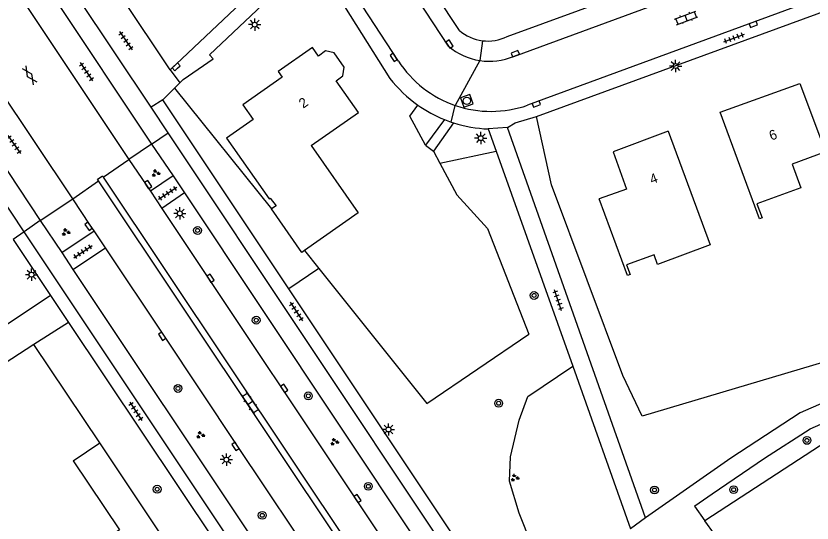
# Model space of a CAD drawing. Extents: x 137999 to 141000, y 397500 to 400501.
# Drawn here: x 138292.8 to 138374, y 399809 to 399860.8 of the extents above; entities that cross this region are included whole.
import ezdxf

# ---------------------------------------------------------------- set-up
doc = ezdxf.new("R2010")
doc.units = 0
for name, color, linetype in [('gg-afsc-erfafscheiding', 7, 'Continuous'), ('gg-afsc-hekwerk', 7, 'Continuous'), ('gg-anno-huisnummerreeks BGT', 7, 'Continuous'), ('gg-bbg-gedigitaliseerde bebouwing', 7, 'Continuous'), ('gg-bbg-hoofdgebouw', 7, 'Continuous'), ('gg-knt-verharding', 7, 'Continuous'), ('gt-grn-groengrens', 7, 'Continuous'), ('gt-grn-groengrens NZ', 7, 'Continuous'), ('gt-grn-weggrens', 7, 'Continuous'), ('gt-symb-boom', 7, 'Continuous'), ('gt-symb-gesloten verharding', 7, 'Continuous'), ('gt-symb-groenvak', 7, 'Continuous'), ('gt-symb-klinker verharding', 7, 'Continuous'), ('gt-symb-kolk', 7, 'Continuous'), ('gt-symb-lichtmast', 7, 'Continuous'), ('gt-symb-rioolschacht', 7, 'Continuous'), ('gt-symb-tegel verharding', 7, 'Continuous')]:
    doc.layers.add(name, color=color, linetype=linetype)

# ---------------------------------------------------------------- blocks, each defined once
blk = doc.blocks.new('gt0-LMAST')
at = {"layer": 'gt-symb-lichtmast'}
for p, q in [((-0.182, 0.173), (-0.447, 0.438)), ((-0.005, 0.246), (-0.005, 0.621)), ((0.172, 0.173), (0.437, 0.438)), ((-0.255, -0.004), (-0.63, -0.004)), ((-0.182, -0.181), (-0.447, -0.446)), ((-0.005, -0.254), (-0.005, -0.629)), ((0.437, -0.446), (0.172, -0.181)), ((0.245, -0.004), (0.62, -0.004))]:
    blk.add_line(p, q, dxfattribs=at)
blk.add_circle((-0.005, -0.004), 0.25, dxfattribs=at)
blk = doc.blocks.new('gt0-TEG1')
at = {"layer": 'gt-symb-tegel verharding'}
for p, q in [((-1.125, 0), (1.125, 0)), ((-0.9, -0.25), (-0.9, 0.25)), ((-0.45, -0.25), (-0.45, 0.25)), ((0, -0.25), (0, 0.25)), ((0.45, -0.25), (0.45, 0.25)), ((0.9, -0.25), (0.9, 0.25))]:
    blk.add_line(p, q, dxfattribs=at)
blk = doc.blocks.new('gt0-KOLK')
at = {"layer": 'gt-symb-kolk'}
blk.add_lwpolyline([(0, 0), (0.375, 0), (0.375, 0.4), (-0.375, 0.4), (-0.375, 0), (0, 0)], dxfattribs=at)
blk = doc.blocks.new('gt0-KL1')
at = {"layer": 'gt-symb-klinker verharding'}
for p, q in [((-1.15, 0.3), (1.15, 0.3)), ((-1, -0.3), (-1, 0.3)), ((-0.5, 0.3), (-0.5, 0.45)), ((0, -0.3), (0, 0.3)), ((0.5, 0.3), (0.5, 0.45)), ((1, -0.3), (1, 0.3)), ((-1.15, -0.3), (1.15, -0.3)), ((-0.5, -0.45), (-0.5, -0.3)), ((0.5, -0.45), (0.5, -0.3))]:
    blk.add_line(p, q, dxfattribs=at)
blk = doc.blocks.new('gt0-RS')
at = {"layer": 'gt-symb-rioolschacht'}
blk.add_lwpolyline([(-0.5, -0.5), (0.5, -0.5), (0.5, 0.5), (-0.5, 0.5)], close=True, dxfattribs=at)
blk.add_circle((0, 0), 0.375, dxfattribs=at)
blk = doc.blocks.new('gt0-GRVAK')
at = {"layer": 'gt-symb-groenvak'}
for p, q in [((-0.11, 0.189), (-0.228, 0.24)), ((-0.182, 0.153), (0.088, 0.153)), ((-0.091, 0.211), (-0.156, 0.322)), ((-0.047, 0.214), (-0.047, 0.393)), ((-0.004, 0.211), (0.061, 0.322)), ((0.015, 0.189), (0.133, 0.24)), ((0.262, -0.052), (0.197, 0.059)), ((0.305, -0.049), (0.305, 0.13)), ((0.349, -0.052), (0.414, 0.059)), ((-0.245, -0.228), (-0.363, -0.177)), ((-0.318, -0.264), (-0.047, -0.264)), ((-0.226, -0.206), (-0.291, -0.095)), ((-0.183, -0.203), (-0.183, -0.024)), ((-0.139, -0.206), (-0.074, -0.095)), ((-0.12, -0.228), (-0.002, -0.177)), ((0.243, -0.074), (0.125, -0.023)), ((0.17, -0.11), (0.441, -0.11)), ((0.368, -0.074), (0.486, -0.023))]:
    blk.add_line(p, q, dxfattribs=at)
blk = doc.blocks.new('gt0-BOOM')
at = {"layer": 'gt-symb-boom'}
for radius in [0.4, 0.2]:
    blk.add_circle((0, 0), radius, dxfattribs=at)
blk = doc.blocks.new('gt0-GESVH1')
at = {"layer": 'gt-symb-gesloten verharding'}
for p, q in [((-0.992, -0.261), (0.008, 0.239)), ((0.008, -0.261), (-0.992, 0.239)), ((0.008, 0.239), (1.008, -0.261)), ((1.008, 0.239), (0.008, -0.261))]:
    blk.add_line(p, q, dxfattribs=at)

msp = doc.modelspace()

# ---------------------------------------------------------------- linework, layer by layer
at = {"layer": 'gg-afsc-erfafscheiding'}
for p, q in [((138308.986, 399853.406), (138318.903, 399841.093)), ((138322.246, 399836.834), (138323.704, 399835.012)), ((138294.647, 399827.265), (138286.056, 399821.721)), ((138301.373, 399817.215), (138294.647, 399827.265))]:
    msp.add_line(p, q, dxfattribs=at)
for points in [[(138433.191, 399848.084), (138405.4, 399835.429), (138379.446, 399826.696), (138356.704, 399819.961), (138354.721, 399824.104), (138347.451, 399843.549), (138345.927, 399850.525)], [(138323.704, 399835.012), (138334.734, 399821.226), (138345.136, 399828.298)]]:
    msp.add_lwpolyline(points, dxfattribs=at)
at = {"layer": 'gg-afsc-hekwerk'}
msp.add_line((138334.609, 399847.597), (138335.425, 399846.958), dxfattribs=at)
msp.add_lwpolyline([(138383.681, 399820.869), (138375.577, 399817.405), (138363.107, 399809.282)], dxfattribs=at)
at = {"layer": 'gg-bbg-gedigitaliseerde bebouwing'}
msp.add_lwpolyline([(138298.656, 399815.395), (138303.374, 399808.352), (138300.181, 399806.213)], dxfattribs=at)
at = {"layer": 'gg-bbg-hoofdgebouw'}
for p, q in [((138364.67, 399850.95), (138372.8, 399853.88)), ((138298.656, 399815.395), (138301.373, 399817.215)), ((138309.343, 399805.318), (138301.373, 399817.215))]:
    msp.add_line(p, q, dxfattribs=at)
for points in [[(138323.694, 399856.668), (138323.07, 399857.55), (138319.58, 399855.1), (138319.98, 399854.53), (138315.96, 399851.69), (138317.03, 399850.19), (138314.31, 399848.3)], [(138325.477, 399854.148), (138326.162, 399854.664), (138326.312, 399855.555), (138325.295, 399856.997), (138324.39, 399857.19), (138323.694, 399856.668)], [(138322.936, 399847.549), (138327.76, 399850.92), (138325.477, 399854.148)], [(138372.8, 399853.88), (138375.393, 399846.896), (138371.999, 399845.636), (138372.886, 399843.245), (138368.414, 399841.586), (138368.936, 399840.18), (138368.683, 399840.086), (138364.67, 399850.95)], [(138314.31, 399848.3), (138318.653, 399842.122), (138318.746, 399842.185), (138319.364, 399841.411), (138318.903, 399841.093)], [(138359.36, 399849), (138353.73, 399846.91), (138355.11, 399843.09), (138352.31, 399842.1)], [(138359.36, 399849), (138363.658, 399837.422), (138358.286, 399835.428), (138357.922, 399836.411), (138355.109, 399835.368), (138355.474, 399834.384), (138355.221, 399834.29), (138352.31, 399842.1)], [(138322.936, 399847.549), (138327.73, 399840.693), (138322.246, 399836.834)], [(138322.246, 399836.834), (138321.976, 399836.644), (138318.903, 399841.093)]]:
    msp.add_lwpolyline(points, dxfattribs=at)
at = {"layer": 'gg-knt-verharding'}
for p, q in [((138342.939, 399858.66), (138387.76, 399875.11)), ((138343.599, 399856.639), (138389.29, 399873.41)), ((138345.927, 399850.525), (138402.79, 399871.3)), ((138391.524, 399868.761), (138345, 399851.65)), ((138295.343, 399864.678), (138306.655, 399847.685)), ((138319.001, 399865.131), (138308.559, 399855.275)), ((138331.831, 399856.157), (138326.65, 399864.11)), ((138293.004, 399863.141), (138304.346, 399846.136)), ((138308.559, 399855.275), (138303.188, 399863.305)), ((138325.36, 399863.29), (138330.971, 399854.398)), ((138306.609, 399851.444), (138299.102, 399862.688)), ((138293.661, 399838.756), (138280.953, 399857.8)), ((138298.605, 399842.126), (138289.029, 399856.437)), ((138285.746, 399854.244), (138295.299, 399839.9)), ((138309.537, 399853.951), (138308.986, 399853.406)), ((138307.787, 399852.222), (138308.986, 399853.406)), ((138320.659, 399832.936), (138307.787, 399852.222)), ((138308.333, 399848.857), (138306.609, 399851.444)), ((138336.532, 399850.195), (138334.609, 399847.597)), ((138337.447, 399849.865), (138335.425, 399846.958)), ((138337.235, 399849.935), (138337.447, 399849.865)), ((138341.01, 399849.24), (138341.821, 399846.962)), ((138357.06, 399809.58), (138342.97, 399849.37)), ((138306.655, 399847.685), (138304.346, 399846.136)), ((138306.655, 399847.685), (138308.839, 399844.454)), ((138341.821, 399846.962), (138349.625, 399825.052)), ((138304.346, 399846.136), (138306.527, 399842.887)), ((138308.839, 399844.454), (138306.527, 399842.887)), ((138308.839, 399844.454), (138309.996, 399842.732)), ((138306.527, 399842.887), (138307.692, 399841.112)), ((138309.996, 399842.732), (138307.692, 399841.112)), ((138309.996, 399842.732), (138335.521, 399804.459)), ((138295.299, 399839.9), (138298.605, 399842.126)), ((138307.692, 399841.112), (138333.203, 399802.905)), ((138295.299, 399839.9), (138297.482, 399836.629)), ((138327.535, 399787.99), (138293.661, 399838.756)), ((138297.482, 399836.629), (138300.797, 399838.842)), ((138301.948, 399837.117), (138300.797, 399838.842)), ((138292.528, 399837.964), (138296.349, 399832.249)), ((138298.633, 399834.905), (138301.948, 399837.117)), ((138297.482, 399836.629), (138298.633, 399834.905)), ((138298.633, 399834.905), (138320.78, 399801.717)), ((138342.884, 399799.636), (138320.659, 399832.936)), ((138296.349, 399832.249), (138298.178, 399829.514)), ((138298.178, 399829.514), (138318.2, 399799.57)), ((138349.625, 399825.052), (138355.53, 399808.47))]:
    msp.add_line(p, q, dxfattribs=at)
for points in [[(138338.06, 399859.28), (138333.32, 399866.48), (138333.43, 399866.58), (138328.09, 399874.79), (138325.56, 399880.89), (138325.96, 399881.05), (138325.201, 399883.127)], [(138336.95, 399857.68), (138326.78, 399873.19), (138325.66, 399875.34), (138323.66, 399880.45), (138322.972, 399882.313)], [(138309.537, 399853.951), (138309.88, 399854.29), (138312.94, 399856.4), (138312.55, 399856.81), (138319.81, 399863.651)], [(138342.97, 399849.37), (138343.76, 399849.86), (138345.927, 399850.525)], [(138342.494, 399797.621), (138336.437, 399806.685), (138308.333, 399848.857)], [(138301.233, 399843.961), (138301.132, 399844.112), (138301.41, 399844.301)], [(138301.41, 399844.301), (138301.628, 399844.449), (138301.724, 399844.305)], [(138301.724, 399844.305), (138327.3, 399806.031), (138327.072, 399805.893)], [(138327.072, 399805.893), (138326.772, 399805.71), (138301.233, 399843.961)], [(138300.797, 399838.842), (138300.383, 399839.421), (138298.605, 399842.126)], [(138435.67, 399841.3), (138422.62, 399837.88), (138408.32, 399833.79), (138400.5, 399831.32), (138381.41, 399824.03), (138372.81, 399820.28), (138365.75, 399815.67), (138357.06, 399809.58)], [(138324.13, 399803.898), (138315.385, 399816.968), (138307.904, 399828.206), (138301.948, 399837.117)], [(138362.065, 399810.787), (138363.83, 399812.03), (138369.17, 399815.67), (138373.86, 399818.67), (138379.36, 399821.06), (138382.962, 399822.511)], [(138362.065, 399810.787), (138362.045, 399810.773), (138363.107, 399809.282)], [(138356.695, 399804.759), (138357.856, 399803.273), (138361.388, 399805.777), (138362.25, 399804.559), (138365.068, 399806.553), (138363.107, 399809.282)]]:
    msp.add_lwpolyline(points, dxfattribs=at)
for centre, radius, start, end in [((138340.972, 399862.684), 4.479, 229.44938, 262.75255), ((138340.971, 399862.684), 4.48, 262.77196, 296.0646), ((138341.116, 399862.541), 6.402, 229.40508, 261.11328), ((138341.118, 399862.544), 6.406, 261.10221, 292.79022), ((138341.308, 399862.354), 11.323, 213.18046, 251.10508), ((138341.526, 399862.581), 13.356, 217.78411, 234.7281), ((138341.528, 399862.59), 13.364, 234.74722, 248.04958), ((138341.307, 399862.354), 11.323, 251.10748, 289.03266), ((138341.558, 399862.705), 13.482, 248.11052, 251.29631), ((138341.515, 399862.586), 13.355, 252.26732, 267.83417)]:
    msp.add_arc(centre, radius, start, end, dxfattribs=at)
at = {"layer": 'gt-grn-groengrens'}
for p, q in [((138333.006, 399850.537), (138333.814, 399851.677)), ((138334.609, 399847.597), (138333.006, 399850.537)), ((138335.425, 399846.958), (138336.071, 399845.753)), ((138323.704, 399835.012), (138320.659, 399832.936)), ((138298.178, 399829.514), (138294.647, 399827.265))]:
    msp.add_line(p, q, dxfattribs=at)
for points in [[(138336.071, 399845.753), (138337.808, 399842.515), (138340.924, 399839.102), (138345.136, 399828.298)], [(138296.349, 399832.249), (138238.026, 399793.327), (138187.762, 399760.012)], [(138347.57, 399802.91), (138346.686, 399804.262), (138345.413, 399806.887), (138344.141, 399810.069), (138343.186, 399813.33), (138343.266, 399815.796), (138344.141, 399819.535), (138345.057, 399821.948), (138349.625, 399825.052)]]:
    msp.add_lwpolyline(points, dxfattribs=at)
at = {"layer": 'gt-grn-groengrens NZ'}
msp.add_line((138336.071, 399845.753), (138341.821, 399846.962), dxfattribs=at)
at = {"layer": 'gt-grn-weggrens'}
for p, q in [((138340.407, 399858.24), (138340.127, 399856.216)), ((138340.127, 399856.216), (138337.641, 399851.641)), ((138308.559, 399855.275), (138309.537, 399853.951)), ((138307.787, 399852.222), (138306.609, 399851.444)), ((138337.235, 399849.935), (138337.641, 399851.641)), ((138342.97, 399849.37), (138341.01, 399849.24)), ((138306.655, 399847.685), (138308.333, 399848.857)), ((138301.724, 399844.305), (138304.346, 399846.136)), ((138298.605, 399842.126), (138301.233, 399843.961)), ((138295.299, 399839.9), (138293.661, 399838.756)), ((138293.661, 399838.756), (138292.528, 399837.964)), ((138357.06, 399809.58), (138355.53, 399808.47))]:
    msp.add_line(p, q, dxfattribs=at)

# ---------------------------------------------------------------- block references
at = {"layer": 'gt-symb-boom'}
for p in [(138311.341, 399838.887), (138345.683, 399832.255), (138317.329, 399829.733), (138309.343, 399822.771), (138322.644, 399822.013), (138342.067, 399821.263), (138373.517, 399817.474), (138307.224, 399812.491), (138328.764, 399812.789), (138357.962, 399812.416), (138366.04, 399812.45), (138317.943, 399809.835)]:
    msp.add_blockref('gt0-BOOM', p, dxfattribs=at)
at = {"layer": 'gt-symb-gesloten verharding', "rotation": -55.51509196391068}
msp.add_blockref('gt0-GESVH1', (138294.213, 399854.722), dxfattribs=at)
at = {"layer": 'gt-symb-groenvak'}
for p in [(138307.07, 399844.729), (138297.895, 399838.71), (138311.628, 399818.022), (138325.303, 399817.32), (138343.702, 399813.656)]:
    msp.add_blockref('gt0-GRVAK', p, dxfattribs=at)
at = {"layer": 'gt-symb-klinker verharding'}
for p, rotation in [((138361.196, 399860.554), 20.482296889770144), ((138316.712, 399821.294), -56.00796028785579)]:
    msp.add_blockref('gt0-KL1', p, dxfattribs=dict(at, rotation=rotation))
at = {"layer": 'gt-symb-kolk'}
for p, rotation in [((138368.114, 399859.726), 20.1739449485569), ((138336.872, 399857.782), -56.91369260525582), ((138343.821, 399856.72), 20.173944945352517), ((138331.185, 399856.419), -56.91369260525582), ((138309.295, 399855.423), 43.337956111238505), ((138345.983, 399851.596), 20.1739449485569), ((138306.139, 399843.451), -56.214572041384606), ((138300.383, 399839.421), 125.59763150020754), ((138312.503, 399833.903), -56.29404346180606), ((138307.904, 399828.206), 123.65827186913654), ((138320.016, 399822.67), -56.214572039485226), ((138315.385, 399816.968), 123.78542795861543), ((138327.503, 399811.436), -56.29404346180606)]:
    msp.add_blockref('gt0-KOLK', p, dxfattribs=dict(at, rotation=rotation))
at = {"layer": 'gt-symb-lichtmast'}
for p in [(138317.179, 399859.882), (138360.127, 399855.657), (138340.238, 399848.307), (138309.537, 399840.625), (138294.413, 399834.381), (138330.824, 399818.586), (138314.291, 399815.517)]:
    msp.add_blockref('gt0-LMAST', p, dxfattribs=at)
at = {"layer": 'gt-symb-rioolschacht', "rotation": 20.1739449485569}
msp.add_blockref('gt0-RS', (138338.821, 399852.102), dxfattribs=at)
at = {"layer": 'gt-symb-tegel verharding'}
for p, rotation in [((138304.018, 399858.241), -55.38819363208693), ((138366.077, 399858.5), 20.247501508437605), ((138299.998, 399855.073), -55.515091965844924), ((138292.635, 399847.651), -55.51509196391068), ((138308.297, 399842.683), 33.2928485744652), ((138299.648, 399836.723), 33.29284857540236), ((138348.116, 399831.764), 109.26841496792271), ((138321.419, 399830.618), -56.500599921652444), ((138305.046, 399820.441), -56.500599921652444)]:
    msp.add_blockref('gt0-TEG1', p, dxfattribs=dict(at, rotation=rotation))

# ---------------------------------------------------------------- texts
at = {"layer": 'gg-anno-huisnummerreeks BGT'}
for s, rotation, p in [('2', 35.3, (138322.121, 399851.293)), ('6', 19.8, (138369.874, 399848.043)), ('4', 20.4, (138357.692, 399843.581))]:
    msp.add_text(s, height=1, rotation=rotation, dxfattribs=at).set_placement(p)

doc.saveas('drawing.dxf')
